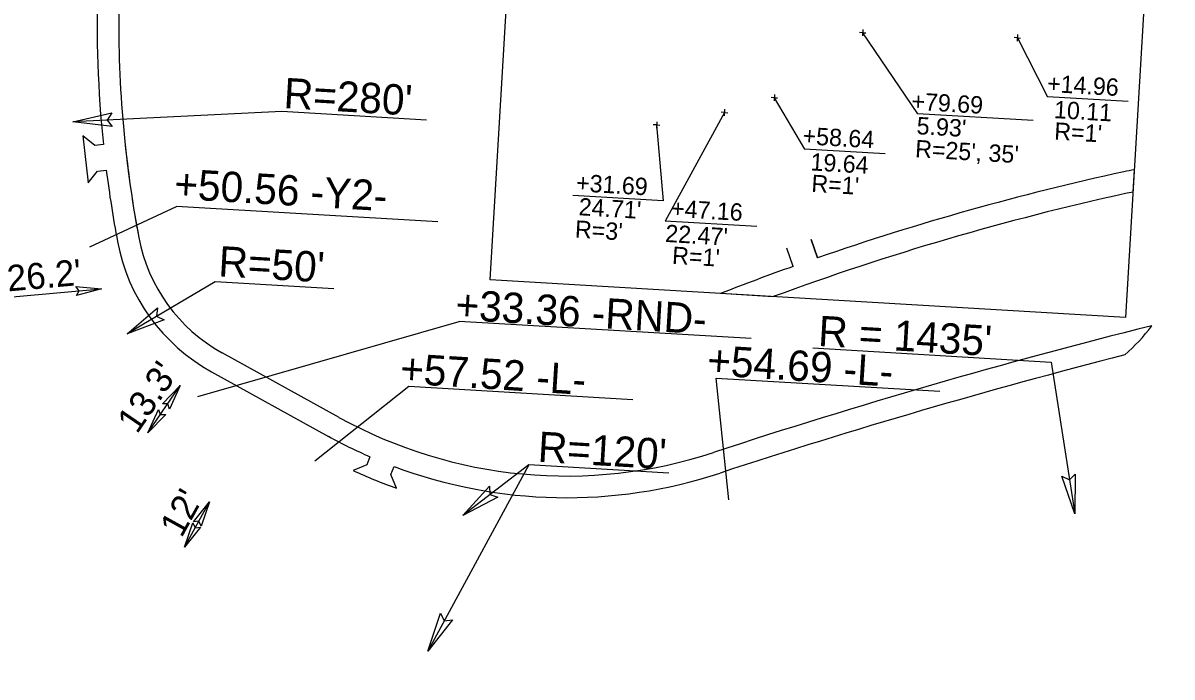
# Model space of a CAD drawing. Extents: x 2012744 to 2013625, y 444638 to 445237.
# Drawn here: x 2013223.7 to 2013488.7, y 444916.9 to 445067.8 of the extents above; entities that cross this region are included whole.
import ezdxf

# ---------------------------------------------------------------- set-up
doc = ezdxf.new("R2010")
doc.units = 0
for name, color, linetype in [('Old_Level_1', 7, 'Continuous'), ('Old_Level_10', 7, 'Continuous'), ('Prop Conc 4in Sidewalk', 7, 'Continuous'), ('Prop Dimension', 7, 'Continuous'), ('Prop Dimension Text', 7, 'Continuous'), ('Prop Shade Medium', 7, 'Continuous'), ('Prop Terminator CELL', 7, 'Continuous')]:
    doc.layers.add(name, color=color, linetype=linetype)

msp = doc.modelspace()

# ---------------------------------------------------------------- linework, layer by layer
at = {"layer": 'Old_Level_1'}
msp.add_lwpolyline([(2013339.03, 445136.98), (2013485.6, 445128.34), (2013478.02, 444999.85), (2013331.46, 445008.49)], close=True, dxfattribs=at)
at = {"layer": 'Prop Conc 4in Sidewalk'}
for p, q in [((2013406.99, 445013.6), (2013405.52, 445017.84)), ((2013401.37, 445011.63), (2013399.86, 445015.87))]:
    msp.add_line(p, q, dxfattribs=at)
msp.add_arc((2013610.78, 444424.35), 623.5, 102.32847, 109.07758, dxfattribs=at)
at = {"layer": 'Prop Dimension'}
for p, q in [((2013417.36, 445065.56), (2013430.04, 445046.85)), ((2013453.07, 445064.38), (2013459.99, 445050.75)), ((2013397, 445050.54), (2013403.97, 445038.66)), ((2013478.61, 445049.65), (2013459.99, 445050.75)), ((2013283.41, 445047.34), (2013235.22, 445044.99)), ((2013316.79, 445045.37), (2013283.41, 445047.34)), ((2013385.49, 445047.13), (2013371.84, 445022.07)), ((2013456.74, 445045.27), (2013430.04, 445046.85)), ((2013369.84, 445044.27), (2013371.35, 445026.74)), ((2013422.59, 445037.57), (2013403.97, 445038.66)), ((2013371.35, 445026.74), (2013350.5, 445027.97)), ((2013319.38, 445021.91), (2013259.13, 445025.46)), ((2013392.98, 445020.83), (2013371.84, 445022.07)), ((2013215.66, 445004.13), (2013241.81, 445006.46)), ((2013268.01, 445008.04), (2013247.72, 444996.1)), ((2013295.42, 445006.42), (2013268.01, 445008.04)), ((2013391.67, 444994.96), (2013324.3, 444998.93)), ((2013460.82, 444989.56), (2013466.28, 444954.53)), ((2013386.53, 444957.75), (2013383.56, 444985.87)), ((2013252.47, 444973.18), (2013259.98, 444984.14)), ((2013291.03, 444966.73), (2013312.73, 444983.97)), ((2013340.36, 444965.81), (2013317.08, 444922.86)), ((2013340.36, 444965.81), (2013325.12, 444954.17)), ((2013372.65, 444963.9), (2013340.36, 444965.81)), ((2013260.92, 444946.8), (2013266.73, 444957.3))]:
    msp.add_line(p, q, dxfattribs=at)
at = {"layer": 'Prop Dimension Text'}
for p, q in [((2013417.36, 445065.56), (2013416.61, 445065.6)), ((2013417.4, 445066.31), (2013417.31, 445064.81)), ((2013417.36, 445065.56), (2013418.11, 445065.52)), ((2013453.07, 445064.38), (2013452.32, 445064.42)), ((2013453.11, 445065.12), (2013453.02, 445063.63)), ((2013453.07, 445064.38), (2013453.81, 445064.33)), ((2013397.04, 445051.29), (2013396.95, 445049.8)), ((2013397, 445050.54), (2013396.25, 445050.59)), ((2013397, 445050.54), (2013397.75, 445050.5)), ((2013385.49, 445047.13), (2013384.74, 445047.18)), ((2013385.53, 445047.88), (2013385.44, 445046.38)), ((2013385.49, 445047.13), (2013386.24, 445047.09)), ((2013369.84, 445044.27), (2013369.09, 445044.32)), ((2013369.88, 445045.02), (2013369.79, 445043.52)), ((2013369.84, 445044.27), (2013370.58, 445044.23)), ((2013239.11, 445016.15), (2013259.13, 445025.46)), ((2013264.06, 444981.63), (2013324.3, 444998.93)), ((2013405.91, 444992.8), (2013460.82, 444989.56)), ((2013383.56, 444985.87), (2013435.21, 444982.83)), ((2013312.73, 444983.97), (2013364.37, 444980.93))]:
    msp.add_line(p, q, dxfattribs=at)
at = {"layer": 'Prop Shade Medium'}
for p, q in [((2013240.27, 445039.56), (2013237.51, 445041.75)), ((2013242.23, 445039.78), (2013240.27, 445039.56)), ((2013238.75, 445030.91), (2013240.89, 445033.59)), ((2013240.95, 445033.6), (2013242.91, 445033.82)), ((2013480.03, 445033.92), (2013479.73, 445028.77)), ((2013405.52, 445017.84), (2013406.99, 445013.6)), ((2013401.37, 445011.63), (2013399.86, 445015.87)), ((2013396.77, 445004.64), (2013384.56, 445005.36)), ((2013296.59, 444976.79), (2013269.62, 444991.7)), ((2013296.59, 444976.79), (2013269.62, 444991.7)), ((2013267.2, 444987.32), (2013294.17, 444972.41)), ((2013267.2, 444987.32), (2013294.17, 444972.41)), ((2013303.73, 444967.7), (2013302.98, 444965.85)), ((2013302.98, 444965.85), (2013299.83, 444964.52)), ((2013308.54, 444963.6), (2013309.29, 444965.45)), ((2013309.87, 444960.46), (2013308.54, 444963.6))]:
    msp.add_line(p, q, dxfattribs=at)
for centre, radius, start, end in [((2013514.28, 445067.92), 273.5, 178.1336, 185.9047), ((2013514.28, 445067.92), 268.5, 178.8864, 190.6549), ((2013514.28, 445067.92), 278, 185.4015, 187.6501), ((2013514.28, 445067.92), 268.5, 185.8936, 190.6549), ((2013514.28, 445067.92), 273.5, 187.1616, 190.6549), ((2013514.28, 445067.92), 273.5, 187.1616, 190.6549), ((2013610.78, 444424.35), 623.5, 102.32847, 109.07758), ((2013486.19, 444994.39), 40, 98.8649, 102.3285), ((2013610.78, 444424.35), 618.5, 102.39734, 110.24384), ((2013486.58, 444989.36), 40, 99.8692, 102.3973), ((2013288.24, 445025.39), 43.5, 190.6549, 241.0711), ((2013288.24, 445025.39), 43.5, 190.6549, 241.0711), ((2013288.24, 445025.39), 38.5, 190.6549, 241.0711), ((2013288.24, 445025.39), 38.5, 190.6549, 241.0711), ((2013610.78, 444424.35), 623.5, 109.62496, 111.27354), ((2013842.57, 443569.75), 1472.5, 104.09144, 108.18835), ((2013842.57, 443569.75), 1472.5, 104.09144, 108.18835), ((2013449.52, 445023.55), 43, 311.2088, 323.4375), ((2013842.57, 443569.75), 1467.5, 104.39059, 108.18835), ((2013842.57, 443569.75), 1467.5, 104.39059, 108.18835), ((2013349.07, 445071.75), 108.5, 241.0711, 288.1883), ((2013349.07, 445071.75), 108.5, 241.0711, 288.1883), ((2013349.07, 445071.75), 113.5, 241.0711, 246.452), ((2013349.07, 445071.75), 113.5, 241.0711, 246.452), ((2013349.07, 445071.75), 118, 245.3337, 250.5951), ((2013349.07, 445071.75), 113.5, 249.4809, 288.1883), ((2013349.07, 445071.75), 113.5, 249.4809, 288.1883), ((2013223.9, 446217.91), 1341.25, 278.35841, 286.14038), ((2013223.9, 446217.91), 1346.25, 278.35841, 286.06498)]:
    msp.add_arc(centre, radius, start, end, dxfattribs=at)
at = {"layer": 'Prop Terminator CELL'}
for points in [[(2013244.28, 445043.88), (2013235.22, 445044.99), (2013244.18, 445047.03), (2013243.11, 445045.37)], [(2013235.89, 445006.95), (2013241.81, 445006.46), (2013236.04, 445004.9), (2013236.69, 445006.01)], [(2013256.27, 444999.33), (2013247.72, 444996.1), (2013254.71, 445002.07), (2013254.53, 445000.11)], [(2013255.84, 444979.89), (2013259.98, 444984.14), (2013257.52, 444978.7), (2013257.08, 444979.91)], [(2013256.61, 444977.44), (2013252.47, 444973.18), (2013254.94, 444978.62), (2013255.37, 444977.42)], [(2013466.42, 444963.66), (2013466.28, 444954.53), (2013463.3, 444963.23), (2013465.06, 444962.34)], [(2013333.22, 444958.4), (2013325.12, 444954.17), (2013331.34, 444960.93), (2013331.4, 444958.96)], [(2013263.02, 444952.67), (2013266.73, 444957.3), (2013264.79, 444951.65), (2013264.24, 444952.81)], [(2013264.64, 444951.43), (2013260.92, 444946.8), (2013262.86, 444952.45), (2013263.41, 444951.29)], [(2013322.73, 444930.03), (2013317.08, 444922.86), (2013319.98, 444931.57), (2013320.84, 444929.8)]]:
    msp.add_lwpolyline(points, close=True, dxfattribs=at)

# ---------------------------------------------------------------- texts
at = {"layer": 'Old_Level_10'}
for s, p in [('+14.96', (2013459.84, 445051.91)), ('+79.69', (2013428.54, 445047.8)), ('10.11', (2013461.43, 445045.86)), ("5.93'", (2013429.74, 445042.15)), ('+58.64', (2013403.44, 445039.84)), ("R=1'", (2013461.49, 445040.89)), ("R=25', 35'", (2013429.4, 445036.84)), ('19.64', (2013405.26, 445033.79)), ('+31.69', (2013351.19, 445028.98)), ("R=1'", (2013405.47, 445028.81)), ("24.71'", (2013351.8, 445023.44)), ('+47.16', (2013373.11, 445023.08)), ("R=3'", (2013350.93, 445018.27)), ("22.47'", (2013371.76, 445017.28)), ("R=1'", (2013373.34, 445012.22))]:
    msp.add_text(s, height=4, rotation=356.6264, dxfattribs=at).set_placement(p)
at = {"layer": 'Prop Dimension Text'}
for s, height, rotation, p in [("R=280'", 7, 356.6264, (2013283.7, 445048.17)), ('+50.56 -Y2-', 7, 356.6264, (2013258.44, 445027.25)), ("R=50'", 7, 356.6264, (2013268.65, 445009.35)), ("26.2'", 6, 5.1016, (2013220.27, 445005.84)), ('+33.36 -RND-', 7, 356.6264, (2013323.29, 444999.36)), ("R = 1435'", 7, 356.6264, (2013406.99, 444993.28)), ('+54.69 -L-', 7, 356.3956, (2013381.36, 444986.55)), ("13.3'", 6, 55.581, (2013250, 444972.78)), ('+57.52 -L-', 7, 356.3956, (2013310.52, 444984.65)), ("R=120'", 7, 356.6264, (2013342.33, 444966.54)), ("12'", 6, 61.0711, (2013260.26, 444948.8))]:
    msp.add_text(s, height=height, rotation=rotation, dxfattribs=at).set_placement(p)

doc.saveas('drawing.dxf')
